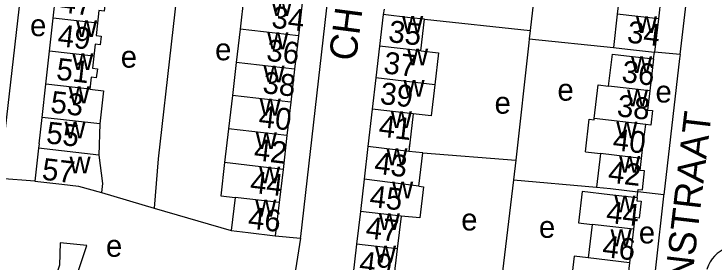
# Model space of a CAD drawing. Extents: x 161258 to 163262, y 380749 to 382054.
# Drawn here: x 162017.3 to 162145.4, y 380978.2 to 381023.7 of the extents above; entities that cross this region are included whole.
import ezdxf

# ---------------------------------------------------------------- set-up
doc = ezdxf.new("R2010")
doc.units = 0
for name, color, linetype in [('BLT_Basislijn', 7, 'Continuous'), ('BLT_Bebouwing', 7, 'Continuous'), ('BLT_Centroide', 7, 'Continuous'), ('BLT_Huisnummer', 7, 'Continuous'), ('BLT_Huisnummer_ tussenligend', 7, 'Continuous'), ('BLT_Onderverdeling_panden', 7, 'Continuous'), ('BLT_Straatnaam', 7, 'Continuous')]:
    doc.layers.add(name, color=color, linetype=linetype)

msp = doc.modelspace()

# ---------------------------------------------------------------- linework, layer by layer
at = {"layer": 'BLT_Basislijn'}
for p, q in [((162014.67, 380993.66), (162020.31, 381042.54)), ((162085.04, 381024.62), (162084.86, 381023.62)), ((162092.45, 381022.75), (162111.74, 381020.7)), ((162111.74, 381020.7), (162111.59, 381019.16)), ((162111.59, 381019.16), (162126.99, 381017.6)), ((162134.35, 381015.5), (162134.52, 381016.72)), ((162139.21, 381016.31), (162134.52, 381016.72)), ((162092.13, 380998.32), (162109.17, 380997.02)), ((162109.17, 380997.02), (162108.72, 380993.4)), ((162021.1, 380993.18), (162014.67, 380993.66)), ((162108.72, 380993.4), (162105.9, 380970.04)), ((162108.72, 380993.4), (162123.92, 380992.1)), ((162131.33, 380990.1), (162131.45, 380991.23)), ((162136.25, 380990.68), (162131.45, 380991.23)), ((162033.31, 380991.07), (162042.95, 380988.26)), ((162042.95, 380988.26), (162057.08, 380984.13)), ((162065.12, 380983.19), (162069.76, 380982.74))]:
    msp.add_line(p, q, dxfattribs=at)
for points in [[(162069.76, 380982.74), (162069.81, 380983.07), (162080.08, 381073.65)], [(162114.56, 381044.94), (162114.47, 381043.95), (162111.8, 381021.23), (162111.74, 381020.7)], [(162139.21, 381016.31), (162142.09, 381040.77), (162142.21, 381041.77)], [(162048.43, 381039.23), (162043.71, 380997.27), (162042.95, 380988.26)], [(162111.59, 381019.16), (162111.52, 381018.43), (162109.17, 380997.02)], [(162139.21, 381016.31), (162139.12, 381015.56), (162136.25, 380990.68)], [(162133.34, 380964.82), (162133.39, 380965.32), (162136.22, 380990.42), (162136.25, 380990.68)], [(162069.76, 380982.74), (162064.53, 380949.92), (162062.75, 380947.85), (162060.42, 380947.53), (162027.86, 380958.03), (162018.65, 380961.28), (162014.44, 380963.06), (162012.21, 380966.06), (162012.13, 380967.45), (162012.32, 380969.43)], [(162149.69, 380981.18), (162149.02, 380981.16), (162148.37, 380981.07), (162147.73, 380980.9), (162147.11, 380980.65), (162146.53, 380980.33), (162145.99, 380979.94), (162145.5, 380979.49), (162145.07, 380978.99), (162144.7, 380978.44), (162144.4, 380977.84), (162144.17, 380977.22), (162144.12, 380977.03)]]:
    msp.add_lwpolyline(points, dxfattribs=at)
at = {"layer": 'BLT_Bebouwing'}
for p, q in [((162128.42, 381029.78), (162127.71, 381023.69)), ((162024.51, 381022.98), (162025.2, 381029.09)), ((162135.94, 381028.9), (162135.23, 381022.81)), ((162070.05, 381025.76), (162069.35, 381019.7)), ((162084.86, 381023.62), (162084.2, 381017.87)), ((162127.71, 381023.69), (162126.99, 381017.6)), ((162023.82, 381016.93), (162024.51, 381022.98)), ((162091.78, 381016.99), (162092.45, 381022.75)), ((162135.23, 381022.81), (162134.52, 381016.72)), ((162069.35, 381019.7), (162068.65, 381013.64)), ((162023.14, 381010.9), (162023.82, 381016.93)), ((162084.2, 381017.87), (162083.52, 381012.06)), ((162134.35, 381015.5), (162133.65, 381009.66)), ((162068.65, 381013.64), (162067.94, 381007.58)), ((162083.52, 381012.06), (162082.86, 381006.35)), ((162022.45, 381004.83), (162023.14, 381010.9)), ((162067.94, 381007.58), (162067.24, 381001.52)), ((162082.86, 381006.35), (162082.08, 380999.5)), ((162090.38, 381005.48), (162089.58, 380998.62)), ((162021.9, 380999.99), (162022.45, 381004.83)), ((162033.04, 381003.63), (162032.86, 380997.95)), ((162056.58, 381002.75), (162055.86, 380996.55)), ((162067.24, 381001.52), (162066.54, 380995.31)), ((162021.79, 380999.21), (162021.1, 380993.18)), ((162021.9, 380999.99), (162021.79, 380999.21)), ((162082.08, 380999.5), (162081.38, 380993.56)), ((162089.67, 380999.37), (162089.74, 381000)), ((162121.91, 380998.52), (162124.63, 380998.2)), ((162124.63, 380998.2), (162123.92, 380992.1)), ((162066.54, 380995.31), (162065.83, 380989.25)), ((162081.38, 380993.56), (162080.69, 380987.62)), ((162057.79, 380990.18), (162057.08, 380984.13)), ((162065.83, 380989.25), (162065.12, 380983.19)), ((162080.69, 380987.62), (162079.99, 380981.68)), ((162088.13, 380986.75), (162087.43, 380980.82)), ((162123.08, 380985.27), (162122.37, 380979.14)), ((162130.67, 380984.38), (162129.96, 380978.26)), ((162079.99, 380981.68), (162079.3, 380975.75)), ((162087.43, 380980.82), (162086.74, 380974.88)), ((162129.96, 380978.26), (162129.24, 380972.05))]:
    msp.add_line(p, q, dxfattribs=at)
for points in [[(162033.31, 381028.17), (162033.05, 381025.86), (162033.99, 381025.74), (162033.83, 381024.21), (162032.85, 381024.33), (162032.59, 381022.06)], [(162059.39, 381027), (162058.69, 381020.94)], [(162092.45, 381022.75), (162089.83, 381023.05), (162084.86, 381023.62)], [(162032.59, 381022.06), (162032.33, 381019.79), (162033.24, 381019.65), (162033.07, 381018.1), (162032.18, 381018.19), (162031.94, 381016.01)], [(162058.69, 381020.94), (162057.99, 381014.88)], [(162091.78, 381016.99), (162094.97, 381016.62), (162094.3, 381010.8)], [(162126.99, 381017.6), (162129.56, 381017.3), (162134.52, 381016.72)], [(162031.94, 381016.01), (162031.69, 381013.83), (162032.58, 381013.7), (162032.38, 381012.05), (162031.42, 381012.17), (162031.17, 381009.99)], [(162126.12, 381010.53), (162126.82, 381016.38), (162129.38, 381016.08), (162134.35, 381015.5)], [(162057.99, 381014.88), (162057.28, 381008.81)], [(162094.3, 381010.8), (162093.63, 381005.1), (162090.38, 381005.48)], [(162123.48, 381004.63), (162124.19, 381010.75), (162126.12, 381010.53)], [(162031.17, 381009.99), (162033.72, 381009.68), (162033.04, 381003.63)], [(162133.65, 381009.66), (162133.24, 381006.17), (162134.16, 381006.06), (162133.86, 381003.43), (162132.92, 381003.54)], [(162057.28, 381008.81), (162056.58, 381002.75)], [(162121.91, 380998.52), (162122.58, 381004.49), (162123.45, 381004.39), (162123.48, 381004.63)], [(162132.16, 380997.3), (162132.41, 380999.48), (162132.92, 381003.54)], [(162032.86, 380997.95), (162033.49, 380992.75), (162033.31, 380991.07)], [(162092.13, 380998.32), (162089.58, 380998.62)], [(162091.41, 380992.25), (162092.13, 380998.32)], [(162055.86, 380996.55), (162055.15, 380990.49), (162057.79, 380990.18)], [(162131.45, 380991.23), (162131.5, 380991.66), (162132.3, 380991.56), (162132.7, 380995.04), (162131.92, 380995.13), (162132.16, 380997.3)], [(162021.1, 380993.18), (162026.07, 380992.6), (162029.14, 380992.24), (162033.31, 380991.07)], [(162091.41, 380992.25), (162092.26, 380992.15), (162091.59, 380986.44), (162088.13, 380986.75)], [(162131.33, 380990.1), (162126.37, 380990.68), (162121.26, 380991.27), (162120.6, 380985.55), (162123.08, 380985.27)], [(162123.92, 380992.1), (162126.49, 380991.81), (162131.45, 380991.23)], [(162131.33, 380990.1), (162131.27, 380989.59), (162132.07, 380989.49), (162131.71, 380986.41), (162130.92, 380986.51), (162130.67, 380984.38)], [(162057.08, 380984.13), (162060.15, 380983.77), (162065.12, 380983.19)], [(162029.03, 380976.49), (162029.08, 380976.67), (162030.67, 380981.38), (162025.79, 380981.89), (162025.64, 380977.82), (162024.69, 380974.98), (162022.48, 380975.22), (162019.14, 380976.33), (162017.75, 380972.18), (162020.61, 380971.22), (162019.2, 380967), (162025.17, 380964.99)], [(162122.37, 380979.14), (162119.79, 380979.44), (162119.07, 380973.23)]]:
    msp.add_lwpolyline(points, dxfattribs=at)
at = {"layer": 'BLT_Onderverdeling_panden'}
for p, q in [((162135.23, 381022.81), (162127.71, 381023.69)), ((162032.59, 381022.06), (162024.51, 381022.98)), ((162069.35, 381019.7), (162058.69, 381020.94)), ((162031.94, 381016.01), (162023.82, 381016.93)), ((162091.78, 381016.99), (162084.2, 381017.87)), ((162068.65, 381013.64), (162057.99, 381014.88)), ((162094.3, 381010.8), (162083.52, 381012.06)), ((162031.17, 381009.99), (162023.14, 381010.9)), ((162133.65, 381009.66), (162126.12, 381010.53)), ((162067.94, 381007.58), (162057.28, 381008.81)), ((162090.38, 381005.48), (162082.86, 381006.35)), ((162033.04, 381003.63), (162022.45, 381004.83)), ((162132.92, 381003.54), (162123.48, 381004.63)), ((162067.24, 381001.52), (162056.58, 381002.75)), ((162032.86, 380997.95), (162021.79, 380999.21)), ((162132.16, 380997.3), (162124.63, 380998.2)), ((162066.54, 380995.31), (162055.86, 380996.55)), ((162091.41, 380992.25), (162081.38, 380993.56)), ((162065.83, 380989.25), (162057.79, 380990.18)), ((162088.13, 380986.75), (162080.69, 380987.62)), ((162130.67, 380984.38), (162123.08, 380985.27)), ((162087.43, 380980.82), (162079.99, 380981.68)), ((162129.96, 380978.26), (162122.37, 380979.14))]:
    msp.add_line(p, q, dxfattribs=at)
msp.add_lwpolyline([(162089.58, 380998.62), (162087.05, 380998.92), (162082.08, 380999.5)], dxfattribs=at)

# ---------------------------------------------------------------- texts
at = {"layer": 'BLT_Centroide'}
for s, p in [('w', (162064.38, 381023.34)), ('w', (162088.33, 381020.31)), ('w', (162131.12, 381020.22)), ('e', (162020.26, 381019.67)), ('w', (162028.66, 381019.5)), ('w', (162063.66, 381017.28)), ('e', (162054.12, 381015.26)), ('e', (162036.85, 381013.91)), ('w', (162089.24, 381014.34)), ('w', (162027.98, 381013.47)), ('w', (162130.21, 381012.91)), ('w', (162062.96, 381011.22)), ('w', (162027.3, 381007.41)), ('w', (162088.58, 381008.59)), ('e', (162116.76, 381007.88)), ('e', (162134.7, 381007.54)), ('w', (162129.48, 381006.84)), ('w', (162062.27, 381005.16)), ('e', (162105.25, 381005.5)), ('w', (162086.27, 381002.88)), ('w', (162026.56, 381001)), ('w', (162127.52, 381000.97)), ('w', (162061.55, 380999.03)), ('w', (162085.45, 380996.09)), ('w', (162027.47, 380994.59)), ('w', (162128.04, 380994.72)), ('w', (162062.16, 380992.75)), ('w', (162086.5, 380990)), ('w', (162127.18, 380987.47)), ('w', (162061.45, 380986.69)), ('w', (162084.06, 380984.22)), ('e', (162099.15, 380984.16)), ('e', (162113.37, 380982.81)), ('e', (162131.65, 380981.79)), ('w', (162126.47, 380981.28)), ('e', (162034.14, 380979.35)), ('w', (162083.37, 380978.28))]:
    msp.add_text(s, height=4, dxfattribs=at).set_placement(p)
at = {"layer": 'BLT_Huisnummer'}
for s, rotation, p in [('35', 353.2012, (162085.69, 381018.63)), ('49', 353.5196, (162025.17, 381017.87)), ('36', 353.3825, (162063.37, 381015.19)), ('36', 353.1946, (162128.38, 381011.3)), ('39', 353.3985, (162084.16, 381007.31)), ('53', 353.5284, (162023.86, 381005.72)), ('40', 353.3809, (162061.94, 381003.09)), ('40', 353.3839, (162126.75, 380998.87)), ('43', 353.3277, (162083.11, 380994.57)), ('57', 353.3169, (162022.29, 380993.46)), ('44', 353.3857, (162125.54, 380985.6)), ('46', 353.3029, (162060, 380984.55)), ('49', 353.3244, (162080.35, 380976.44))]:
    msp.add_text(s, height=4, rotation=rotation, dxfattribs=at).set_placement(p)
at = {"layer": 'BLT_Huisnummer_ tussenligend'}
for s, rotation, p in [('47', 353.5203, (162025.56, 381024.05)), ('34', 353.3851, (162064.31, 381021.23)), ('34', 353.3476, (162129.37, 381018.52)), ('37', 353.2012, (162084.81, 381012.9)), ('51', 353.5196, (162024.93, 381011.74)), ('38', 353.3825, (162062.69, 381009.28)), ('38', 353.1946, (162127.52, 381005.05)), ('55', 353.5284, (162023.08, 381000.1)), ('41', 353.3985, (162083.91, 381001.35)), ('42', 353.3809, (162061.09, 380997.01)), ('42', 353.3839, (162125.89, 380992.96)), ('44', 353.3809, (162060.38, 380991.1)), ('45', 353.3277, (162082.24, 380988.49)), ('47', 353.3277, (162081.53, 380982.75)), ('46', 353.3857, (162124.85, 380979.34))]:
    msp.add_text(s, height=4, rotation=rotation, dxfattribs=at).set_placement(p)
at = {"layer": 'BLT_Straatnaam'}
for s, rotation, p in [('CHRYSANTENSTRAAT', 82.6677, (162079.87, 381014.98)), ('CYCLAMENSTRAAT', 83.2896, (162137.55, 380942.48))]:
    msp.add_text(s, height=5, rotation=rotation, dxfattribs=at).set_placement(p)

doc.saveas('drawing.dxf')
